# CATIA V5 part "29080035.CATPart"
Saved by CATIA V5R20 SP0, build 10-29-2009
Part number: 29080035
Definition: NONE
Nomenclature: 29080035
Source: Unknown
Description: 29080035
Bounding box of the stored display mesh (mm): x -17.5 to 44.548, y -54 to 88.548, z -44 to 44
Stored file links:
  C:\Users\Utente\Desktop\IO LAVORO\3D X SITO CF\X SITO\PLASTICA\RF1\29080035.CATPart

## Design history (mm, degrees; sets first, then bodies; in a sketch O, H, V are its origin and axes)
Body1 "29080035" (main body)
  Solid1: solid without history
